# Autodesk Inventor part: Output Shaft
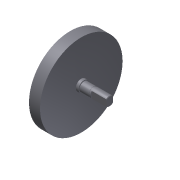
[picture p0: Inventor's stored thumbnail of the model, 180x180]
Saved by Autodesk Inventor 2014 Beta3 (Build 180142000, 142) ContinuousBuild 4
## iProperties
Created: 2011-01
Part Number: Output Shaft
Material: Steel
Document SubType Name: Modeling
Designer: Beta-8540w
Density: 1 g/cm^3
Appearance: Steel
CustomPartVersion: 1
Author: Beta-8540w
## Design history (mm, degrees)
sketch "Main Sketch"
  geometry: L1 (0, 0)-(43, 0) reference; L2 (0, 0)-(0, 45); L3 (12, 45)-(12, 6); L4 (0, 45)-(12, 45); L5 (15, 6)-(15, 5); L6 (12, 6)-(15, 6); L7 (43, 5)-(43, 0); L8 (15, 5)-(43, 5)
  constraints: 16 end point, 5 horizontal, 4 vertical
  dimensions: "d3" = 90 diameter of L4 L1 (derived); "d4" = 12 diameter of L6 L1 (derived); "d5" = 10 diameter of L8 L1 (derived)
revolve "Revolution1" sketch "Main Sketch" stored, may be unused: angle "d6" = 0 deg
chamfer "Chamfer1" distance "d7" = 0.5; stored, may be unused: second distance "d8" = 0.125, angle "d9" = 45 deg
node "Retaining Ring Groove1"
sketch "Sketch3"
  geometry: L1 (-3.571, 3.5)-(3.571, 3.5); L2 (-3.571, -3.5)-(3.571, -3.5); A1 r 5 centre (0, 0) between (-3.571, 3.5) and (3.571, 3.5) reference
  constraints: 4 end point, 4 point on circle, 2 parallel, 1 horizontal
  dimensions: "d10" = 7 distance between parallel lines of L2 L1
extrude "Extrusion1" cut sketch "Sketch3" distance "d11" = 16; taper "d12" = 0 deg
node "Spur Gear Teeth1"
node "Hole2"
body "Solid1"
feature "iFeature27:1"
feature "Spur Gear2"
sketch "Sketch4"
  geometry: 1 further point
hole "Hole1" sketch "Sketch4" diameter "d13" = 3.242; stored, may be unused: countersink angle "d17" = 90 deg, drill point angle "d19" = 120 deg; dims "d14" = 9.49, "d15" = 4, "d16" = 2, "d18" = 11.49
other parameters: "d0" = 0, "d1" = 0, "d2" = 0
